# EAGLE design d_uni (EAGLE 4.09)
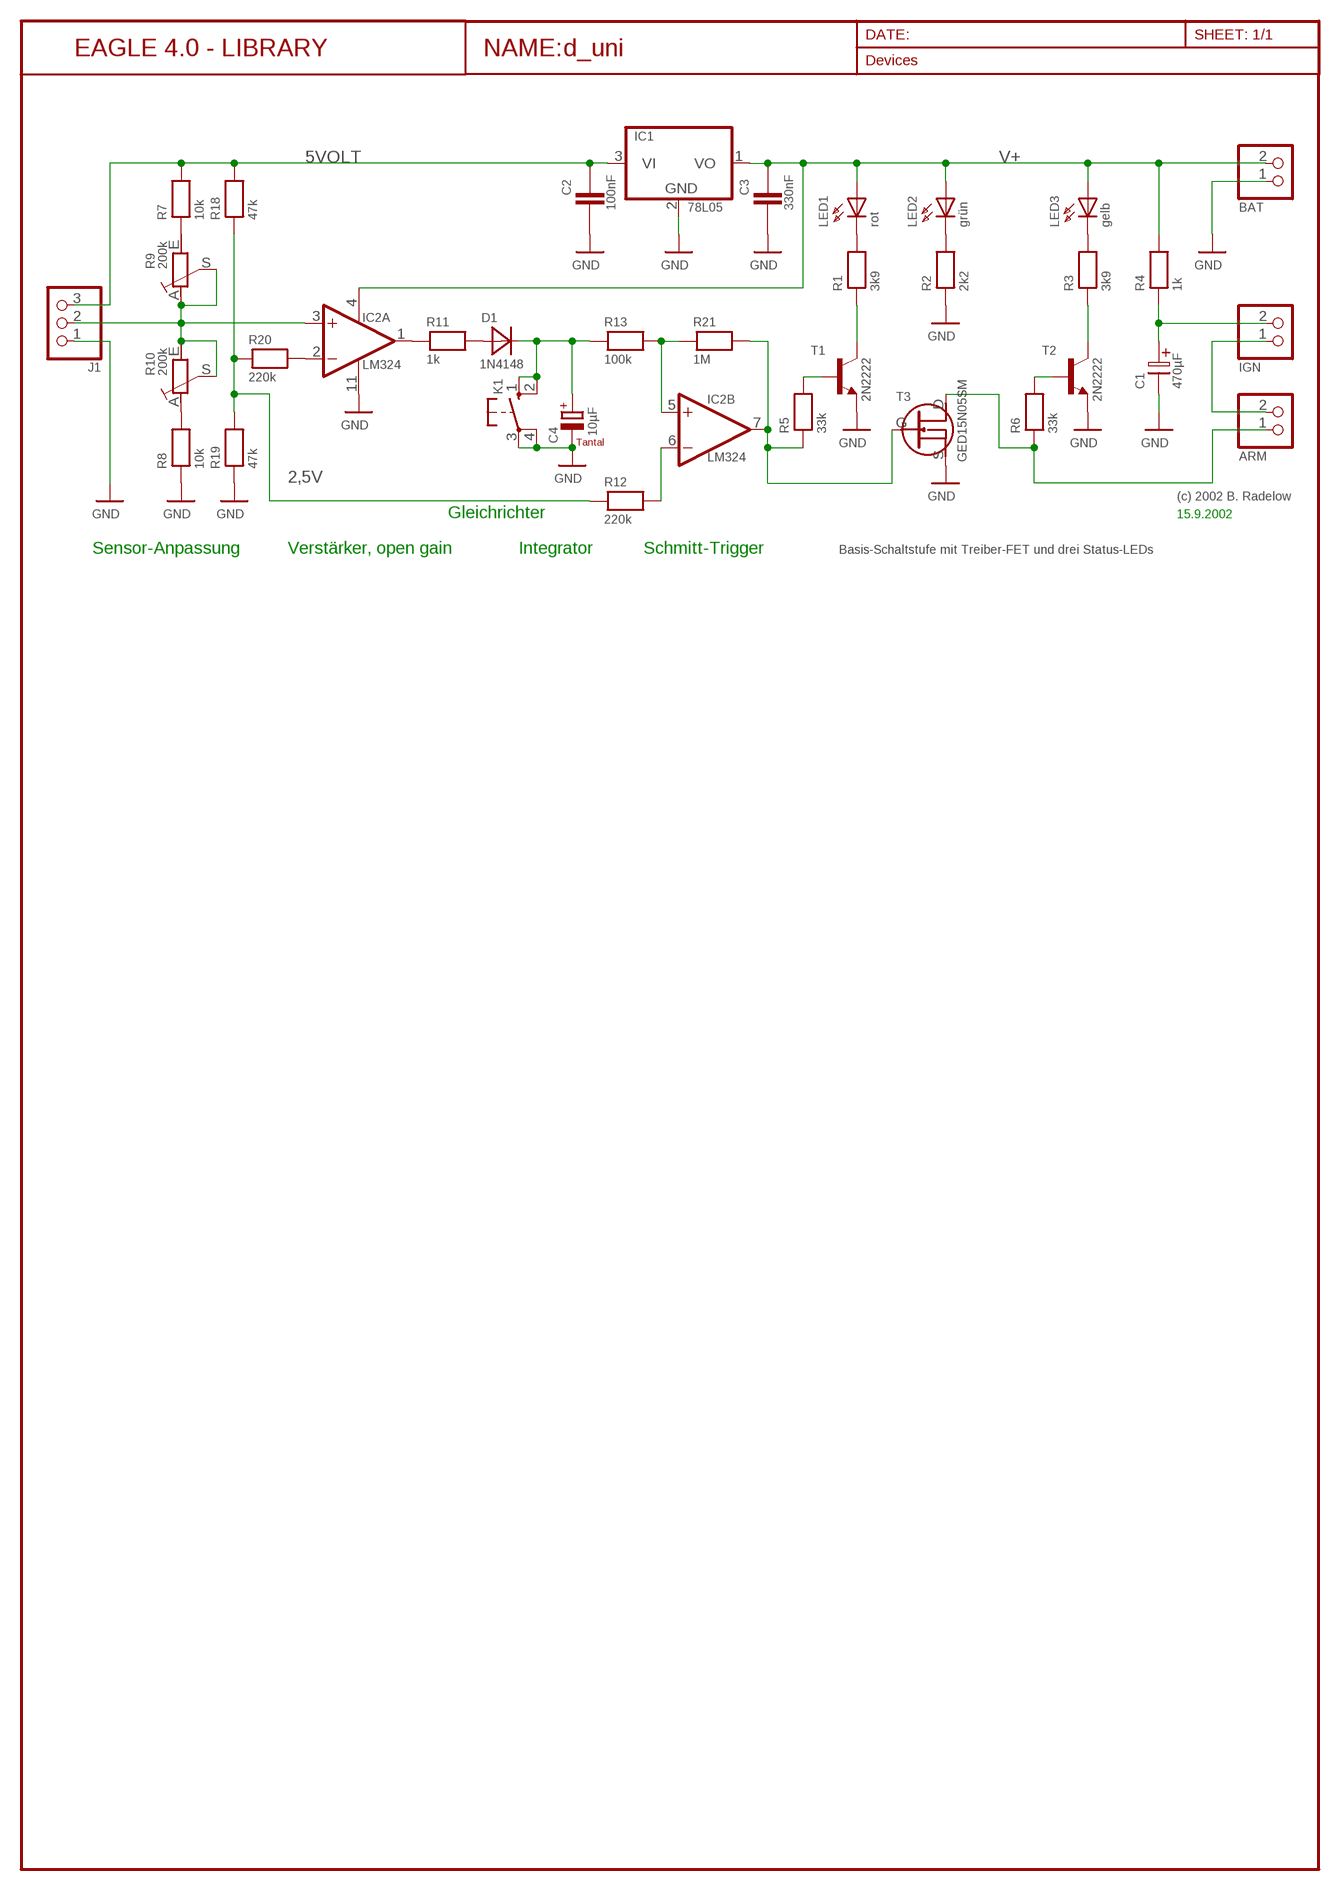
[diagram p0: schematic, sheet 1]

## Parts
ARM  PFOSTEN_1X2  [1X02]
BAT  PFOSTEN_1X2  [1X02]
C1  470µF  EC_470U  [E5-10,5]
C2  100nF  MKS2_10N-150N  [C5B2.5]
C3  330nF  MKS2_330N  [C5B3.5]
C4  10µF  TT_10  [TT2D5]
D1  1N4148  [DO35-7]
IC1  78L05  [TO92]
IC2  LM324  [DIL14]
IGN  PFOSTEN_1X2  [1X02]
J1  PFOSTEN_1X3  [1X03]
K1  TASTER_OMRON  [B3F-10XX]
LED1  rot  LED_3MM  [LED3MM]
LED2  grün  LED_3MM  [LED3MM]
LED3  gelb  LED_3MM  [LED3MM]
R1  3k9  R7,5  [0207/7]
R2  2k2  R7,5  [0207/7]
R3  3k9  R7,5  [0207/7]
R4  1k  R7,5  [0207/7]
R5  33k  R7,5  [0207/7]
R6  33k  R7,5  [0207/7]
R7  10k  R7,5  [0207/7]
R8  10k  R7,5  [0207/7]
R9  200k  TRIM-S64Y  [S64Y]
R10  200k  TRIM-S64Y  [S64Y]
R11  1k  R7,5  [0207/7]
R12  220k  R7,5  [0207/7]
R13  100k  R7,5  [0207/7]
R18  47k  R7,5  [0207/7]
R19  47k  R7,5  [0207/7]
R20  220k  R7,5  [0207/7]
R21  1M  R7,5  [0207/7]
T1  2N2222  [TO18]
T2  2N2222  [TO18]
T3  GED15N05SM  [TO252]

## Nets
2,5V: R12.1 R18.1 R19.2 R20.1
5VOLT: C2.1 IC1.3(VI) J1.3 R7.2 R18.2
GND: BAT.1 C1.- C2.2 C3.2 C4.- IC1.2(GND) IC2.11(A:GND) J1.1 K1.3(P) K1.4(P1) R2.1 R8.1 R19.1 T1.1(E) T2.1(E) T3.S
N$1: ARM.2 IGN.1
N$2: LED2.K(C) R2.2
N$3: LED1.K(C) R1.2
N$4: LED3.K(C) R3.2
N$6: IC2.7(B:OUT) R5.1 R21.2 T3.G
N$8: ARM.1 R6.1 T3.D
N$11: C1.+ IGN.2 R4.1
N$12: C4.+ D1.K K1.1(S) K1.2(S1) R13.1
N$16: IC2.1(A:OUT) R11.1
N$17: R1.1 T1.3(C)
N$18: IC2.6(B:-IN) R12.2
N$19: R7.1 R9.E(1E)
N$20: R5.2 T1.2(B)
N$21: D1.A R11.2
N$22: IC2.2(A:-IN) R20.2
N$23: R8.2 R10.A(1A)
N$24: IC2.3(A:+IN) J1.2 R9.A(1A) R9.S(1S) R10.E(1E) R10.S(1S)
N$25: R3.1 T2.3(C)
N$26: IC2.5(B:+IN) R13.2 R21.1
N$27: R6.2 T2.2(B)
V+: BAT.2 C3.1 IC1.1(VO) IC2.4(A:V+) LED1.A LED2.A LED3.A R4.2
Unconnected: IC2.8(C:OUT) IC2.9(C:-IN) IC2.10(C:+IN) IC2.12(D:+IN) IC2.13(D:-IN) IC2.14(D:OUT)

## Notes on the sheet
- (c) 2002 B. Radelow
- Gleichrichter | 15.9.2002
- Sensor-Anpassung | Verstärker, open gain | Integrator | Schmitt-Trigger | Basis-Schaltstufe mit Treiber-FET und drei Status-LEDs

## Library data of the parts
ARM BAT IGN = _d_serie:PFOSTEN_1X2: Pfosten 2x1
C1 = _d_serie:EC_470U: 470µF 16V, Höhe 17mm
C2 = _d_serie:MKS2_10N-150N: WIMA MKS2 Folienkondensator
C3 = _d_serie:MKS2_330N: WIMA MKS2 Folienkondensator 330nF
C4 = _d_serie:TT_10: Tantal-EC 10µF
D1 = _d_serie:1N4148: Silizium-Diode, Kleinleistung
IC1 = _d_serie:78L05: Voltage Regulator 5V
IC2 = _d_serie:LM324: LM324 - quad OpAmp
J1 = _d_serie:PFOSTEN_1X3: Pfosten 3x1
K1 = _d_serie:TASTER_OMRON: Taster, Omron
LED1-LED3 = _d_serie:LED_3MM
R1-R8 R11-R13 R18-R21 = _d_serie:R7,5: Widerstand 0,3 Watt liegend
R9 R10 = _d_serie:TRIM-S64Y: Trimmer S64Y
T1 T2 = _d_serie:2N2222
T3 = _d_serie:GED15N05SM: N-Channel Power-FET

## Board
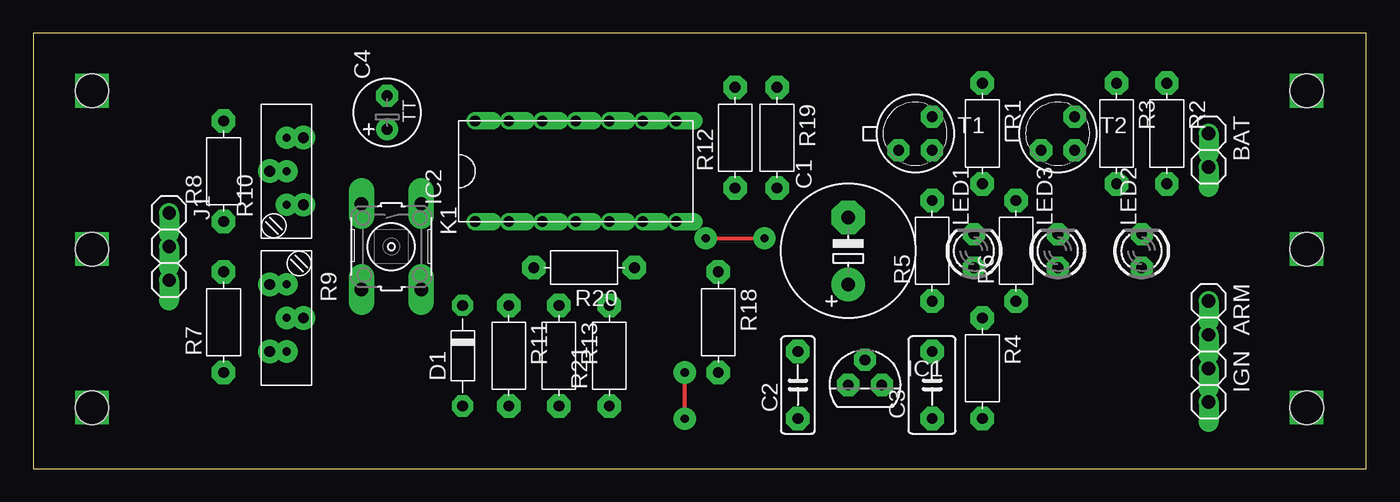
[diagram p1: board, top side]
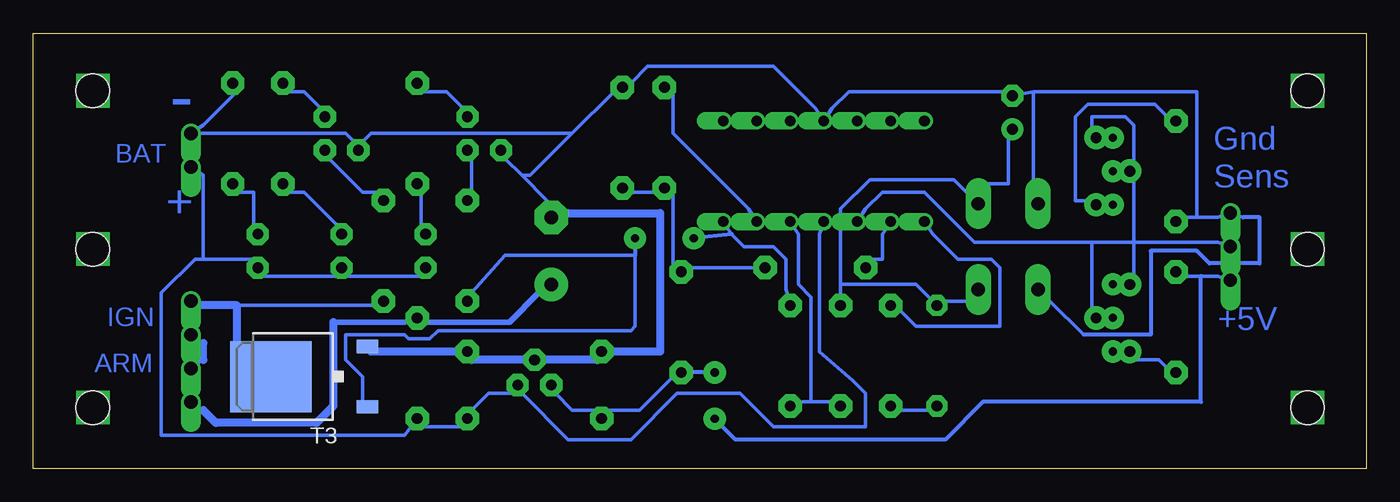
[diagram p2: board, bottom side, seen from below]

Size 101 x 33 mm. Coordinates in mm from the lower left corner, seen from the top.
Outline: 0,0 101,0 101,33 0,33 0,0
Copper layers used: Top, Bottom
Holes 2.54 mm at 96.47,16.63 96.47,28.63 96.47,4.63 4.47,4.63 4.47,16.63 4.47,28.63
tRestrict: area -0.8,-0.6 to 100.8,33.7

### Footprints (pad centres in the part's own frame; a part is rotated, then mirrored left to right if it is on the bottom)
1X02 = drill 1.016 offset: 1 -1.27,0; 2 1.27,0
E5-10,5 = drill 1.016 pad 2.54 round: + -2.54,0 | drill 1.016 pad 2.54 octagon: - 2.54,0
C5B2.5 = drill 0.813 pad 1.778 octagon: 1 -2.54,0; 2 2.54,0
C5B3.5 = drill 0.813 pad 1.778 octagon: 1 -2.54,0; 2 2.54,0
TT2D5 = drill 0.813 pad 1.676 round: + -1.27,0 | drill 0.813 pad 1.676 octagon: - 1.27,0
DO35-7 = drill 0.813 pad 1.6 octagon: A -3.81,0; K 3.81,0
TO92 = drill 0.813 pad 1.676 octagon: 1 1.27,0; 2 0,1.905; 3 -1.27,0
DIL14 = drill 0.813 offset: 1 -7.62,-3.81; 2 -5.08,-3.81; 3 -2.54,-3.81; 4 0,-3.81; 5 2.54,-3.81; 6 5.08,-3.81; 7 7.62,-3.81; 8 7.62,3.81; 9 5.08,3.81; 10 2.54,3.81; 11 0,3.81; 12 -2.54,3.81; 13 -5.08,3.81; 14 -7.62,3.81
1X03 = drill 1.016 offset: 1 -2.54,0; 2 0,0; 3 2.54,0
B3F-10XX = drill 1.016 pad 1.93 long: 1 -3.251,2.261; 2 3.251,2.261; 3 -3.251,-2.261; 4 3.251,-2.261
LED3MM = drill 0.813 pad 1.676 octagon: A -1.27,0; K 1.27,0
0207/7 = drill 0.813 pad 1.778 octagon: 1 -3.81,0; 2 3.81,0
S64Y = drill 0.813 pad 1.778 round: A -2.54,-1.27; E 2.54,-1.27; S 0,1.27
TO18 = drill 0.813 pad 1.676 octagon: 1 -1.27,-1.27; 2 1.27,-1.27; 3 1.27,1.27
TO252 = smd 5.4 x 6.2: D 0,1.23 | smd 1 x 1.6: G -2.28,-6.07; S 2.28,-6.07

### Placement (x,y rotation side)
ARM  89.05,11.43 270 top
BAT  89.05,24.12 270 top
C1  61.75,16.5 90 top
C2  57.94,6.34 90 top
C3  68.1,6.34 90 top
C4  26.82,26.98 90 top
D1  32.54,8.57 90 top
IC1  63.02,6.34 0 top
IC2  41.11,22.54 0 top
IGN  89.05,6.34 270 top
J1  10.31,16.82 270 top
K1  27.14,16.82 270 top
LED1  71.27,16.5 90 top
LED2  83.97,16.5 90 top
LED3  77.62,16.5 90 top
R1  71.91,25.39 270 top
R2  85.88,25.39 270 top
R3  82.07,25.39 270 top
R4  71.91,7.62 270 top
R5  68.1,16.5 90 top
R6  74.45,16.5 90 top
R7  14.44,11.11 90 top
R8  14.44,22.54 90 top
R9  19.2,11.43 270 top
R10  19.2,22.54 90 top
R11  36.03,8.57 270 top
R12  53.17,25.08 90 top
R13  39.84,8.57 270 top
R18  51.91,11.11 270 top
R19  56.35,25.08 270 top
R20  41.74,15.24 180 top
R21  43.65,8.57 90 top
T1  66.83,25.39 0 top
T2  77.62,25.39 0 top
T3  81.75,6.98 90 bottom

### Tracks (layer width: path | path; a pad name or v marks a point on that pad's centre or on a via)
2,5V
  Bottom 0.254: R19.2 55.71,20.95 53.81,20.95 R12.1 52.54,20.95 52.54,15.24 R18.1 51.27,15.24 R20.1
5VOLT  (via drill 0.61 pad 1.68)
  Top 0.305: v49.37,3.8 v49.37,7.3
  Bottom 0.254: J1.3 11.27,14.6 12.54,14.6 13.81,14.6 R7.2 | IC1.3 61.43,5.71 60.16,4.44 58.25,4.44 C2.1 57.62,4.44 55.08,4.44 52.54,6.98 R18.2
  Bottom 0.305: v49.37,7.3 R18.2 | v49.37,3.8 47.78,2.22 31.9,2.22 29.04,5.08 12.54,5.08 12.54,14.6
GND
  Bottom 0.254: 12.85,19.04 13.81,19.04 R8.1 | 12.85,19.04 11.27,19.04 J1.1 9.36,19.04 | 21.42,10.16 23.96,12.7 K1.4 | 25.23,28.57 25.23,21.58 K1.3 | 25.23,28.57 C4.- 27.14,28.57 39.2,28.57 40.48,27.3 IC2.11 41.74,27.3 44.92,30.47 54.45,30.47 55.71,29.2 R19.1 56.98,28.57 60.16,25.39 | C2.2 58.25,8.25 | 75.4,8.89 T3.S | 67.78,8.25 C3.2 | R2.1 85.56,28.57 88.1,26.03 BAT.1 77.3,25.39 76.67,24.76 T2.1 76.03,24.76 75.4,25.39 60.16,25.39 | 63.97,22.22 62.06,20.31 C1.- 60.48,19.36 | 63.97,22.22 65.24,23.49 T1.1 | 60.16,25.39 63.34,22.22 63.97,22.22 | 12.85,19.04 12.85,28.57 25.23,28.57
  Bottom 0.305: 9.36,19.04 8.09,19.04 8.09,15.55 11.9,15.55 12.85,16.5 16.34,16.5 16.34,10.16 21.42,10.16
  Bottom 0.61: 58.25,8.25 IC1.2 67.78,8.25 | C3.2 75.4,8.89 | 60.48,19.36 53.49,19.36 53.49,8.89 C2.2
N$1
  Bottom 0.254: IGN.1 88.1,8.25 | 88.1,9.52 ARM.2
  Bottom 0.61: 88.1,8.25 88.1,9.52
N$2
  Bottom 0.254: LED2.K 84.29,18.41 84.29,20.95 85.56,20.95 R2.2
N$3
  Bottom 0.254: LED1.K 71.59,18.41 71.59,20.95 R1.2
N$4
  Bottom 0.254: LED3.K 77.94,18.41 80.48,20.95 81.75,20.95 R3.2
N$5  (via drill 0.61 pad 2.54)
  other vias: 96.47,28.63
N$6  (via drill 0.61 pad 1.68)
  Top 0.305: v50.95,17.46 v55.4,17.46
  Bottom 0.254: T3.G 76.03,5.08 76.03,6.98 77.3,8.25 77.3,10.16 72.86,10.16 72.54,9.84 70.95,9.84 70.32,10.47 55.71,10.47 55.4,10.79 55.4,16.19 65.24,16.19 67.78,13.33 R5.1 | IC2.7 48.09,17.77 47.14,16.82 44.92,16.82 43.97,15.87 43.97,13.65 R21.2
  Bottom 0.305: 48.09,17.77 v50.95,17.46 | v55.4,17.46 55.4,16.19
N$7  (via drill 0.61 pad 2.54)
  other vias: 96.47,16.63
N$8
  Bottom 0.254: 88.42,12.38 ARM.1 | 85.56,9.52 T3.D | 85.56,12.38 75.4,12.38 R6.1
  Bottom 0.61: 85.56,9.52 85.56,12.38 88.42,12.38
N$9  (via drill 0.61 pad 2.54)
  other vias: 96.47,4.63
N$10  (via drill 0.61 pad 2.54)
  other vias: 4.47,4.63
N$11
  Bottom 0.254: 88.1,4.44 IGN.2 | R4.1 72.86,11.11 | C1.+ 62.7,13.33
  Bottom 0.305: 71.27,11.11 R4.1
  Bottom 0.406: 72.86,11.11 78.26,11.11 | 62.7,13.33 64.92,11.11 71.27,11.11
  Bottom 0.61: 88.1,4.44 87.15,3.49 79.53,3.49 78.26,4.76 78.26,11.11
N$12
  Bottom 0.254: C4.+ 27.14,25.39 27.14,21.58 29.04,21.58 K1.1 30.31,20.95 31.27,21.9 37.62,21.9 39.84,19.68 39.84,13.97 | K1.2 30.31,12.7 32.22,12.7 D1.K 34.12,13.97 39.84,13.97 | 39.84,13.97 R13.1
N$13  (via drill 0.61 pad 2.54)
  other vias: 4.47,16.63
N$14  (via drill 0.61 pad 2.54)
  other vias: 4.47,28.63
N$15  (via drill 0.61 pad 1.68)
  other vias: 19.2,11.43
N$16
  Bottom 0.254: IC2.1 32.85,17.77 30.95,15.87 28.41,15.87 27.77,15.24 27.77,10.79 34.12,10.79 35.39,12.06 R11.1
N$17
  Bottom 0.254: T1.3 68.41,27.3 69.69,28.57 71.59,28.57 R1.1
N$18
  Bottom 0.254: IC2.6 46.82,19.68 52.54,25.39 52.54,28.57 R12.2
N$19
  Bottom 0.254: R7.1 15.08,7.62 15.71,8.25 17.61,8.25 R9.E
N$20
  Bottom 0.254: T1.2 67.78,23.49 67.78,20.95 R5.2
N$21
  Bottom 0.254: D1.A 32.85,4.44 35.39,4.44 R11.2
N$22
  Bottom 0.254: IC2.2 36.66,17.77 36.66,15.87 37.94,15.87 R20.2
N$23
  Bottom 0.254: R8.2 15.08,26.66 16.03,27.62 21.11,27.62 22.06,26.66 22.06,20.31 20.79,20.31 R10.A
N$24
  Bottom 0.254: 17.61,17.14 11.27,17.14 J1.2 | 17.61,17.14 20.79,17.14 | 20.79,17.14 29.68,17.14 33.49,20.95 36.66,20.95 37.94,19.68 IC2.3 | 17.61,17.14 17.61,14.6 R9.A | 17.61,17.14 17.61,22.22 R10.S 17.61,22.86 17.61,26.03 18.25,26.66 20.79,26.66 20.79,25.39 R10.E | 20.79,17.14 20.79,12.06 R9.S
N$25
  Bottom 0.254: T2.3 79.21,27.3 80.48,28.57 81.75,28.57 R3.1
N$26
  Bottom 0.254: 42.06,5.08 42.06,13.01 43.02,13.97 43.02,17.77 IC2.5 | 42.06,5.08 42.7,5.08 R21.1 | 42.06,5.08 40.48,5.08 R13.2
N$27
  Bottom 0.254: T2.2 78.58,23.49 76.03,20.95 74.77,20.95 R6.2
N$28  (via drill 0.61 pad 1.68)
  other vias: 19.2,8.89
N$29  (via drill 0.61 pad 1.68)
  other vias: 19.2,13.97
N$30  (via drill 0.61 pad 1.68)
  other vias: 19.2,20
N$31  (via drill 0.61 pad 1.68)
  other vias: 19.2,22.54
N$32  (via drill 0.61 pad 1.68)
  other vias: 19.2,25.08
V+
  Bottom 0.254: LED1.A 71.59,14.6 77.3,14.6 LED3.A 77.94,14.6 83.66,14.6 LED2.A 84.29,15.87 88.1,15.87 | 88.1,15.87 88.1,22.22 BAT.2 | 88.1,15.87 88.73,15.87 91.28,13.33 91.28,2.54 72.86,2.54 R4.2 71.59,3.17 68.41,3.17 C3.1 67.78,4.44 66.51,5.71 64.61,5.71 IC1.1 63.97,5.71 60.48,2.22 55.71,2.22 52.22,5.71 47.46,5.71 44.92,3.17 37.94,3.17 37.94,5.71 38.89,6.66 41.43,8.89 41.43,17.77 IC2.4

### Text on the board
Bottom: - | Gnd | BAT | Sens | + | +5V | IGN | ARM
